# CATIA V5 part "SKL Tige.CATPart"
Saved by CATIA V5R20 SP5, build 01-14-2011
Part number: SKL Tige
Publications: "Plan.1", "Droite.1", "Point.2", "Droite.2"
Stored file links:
  G:\IAO Final\SKL Tige.CATPart
  G:\IAO Final\Assemblage Final.CATProduct
  G:\IAO Final\SKL Roue.CATPart
  G:\Nouveau dossier (2)\Roue.CATPart
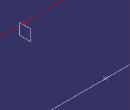
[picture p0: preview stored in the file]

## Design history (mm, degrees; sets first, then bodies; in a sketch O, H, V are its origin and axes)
Set1
  Point1: linked copy from another document
Body1 (main body)
  Plane1: type Offset, RefPlane yz-plane, Offset 0
  Line1: type Normal, RefPoint Point1, RefSkin Plane1, Start 0, End 20
  Point2: type OnPlane, Support Plane1, H 535, V 0, Direction (0, 1, 0)
  Line2: type Normal, RefPoint Point2, RefSkin Plane1, Start 0, End 20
